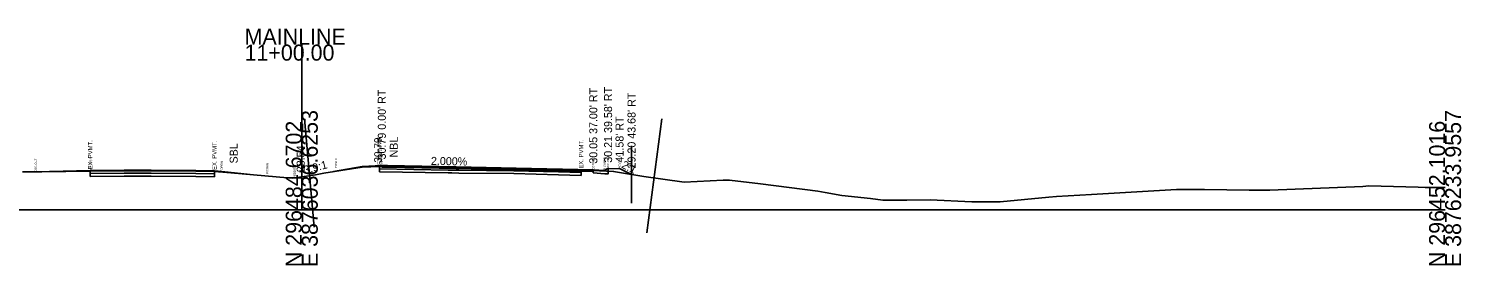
# Model space of a CAD drawing. Extents: x 14823 to 15251, y 114839 to 117377.
# Drawn here: x 15000.6 to 15251.2, y 116838.7 to 116880.1 of the extents above; entities that cross this region are included whole.
import ezdxf

# ---------------------------------------------------------------- set-up
doc = ezdxf.new("R2010")
doc.units = 0
for name, color, linetype in [('Default', 7, 'Continuous'), ('Level 1', 7, 'Continuous'), ('Level 10', 7, 'Continuous'), ('Level 11', 7, 'Continuous'), ('Level 2', 7, 'Continuous'), ('Level 25', 7, 'Continuous'), ('Level 3', 7, 'Continuous'), ('Level 4', 7, 'Continuous'), ('Level 42', 7, 'Continuous'), ('Level 49', 7, 'Continuous'), ('Level 50', 7, 'Continuous'), ('Level 51', 7, 'Continuous'), ('Level 52', 7, 'Continuous'), ('Level 53', 7, 'Continuous'), ('Level 56', 7, 'Continuous'), ('Level 59', 7, 'Continuous'), ('Level 63', 7, 'Continuous')]:
    doc.layers.add(name, color=color, linetype=linetype)

msp = doc.modelspace()

# ---------------------------------------------------------------- linework, layer by layer
at = {"layer": 'Default'}
for p, q in [((15048.86, 116864.32), (15050.53, 116845.37)), ((15111.37, 116864.32), (15108.71, 116844.37))]:
    msp.add_line(p, q, dxfattribs=at)
at = {"layer": 'Level 1'}
for p, q in [((15058.93, 116855.83), (15061.94, 116855.95)), ((15061.94, 116855.95), (15073.95, 116855.76)), ((14999.53, 116855.01), (15002.9, 116855.04)), ((15002.9, 116855.04), (15011.36, 116855.15)), ((15011.36, 116855.15), (15017.29, 116855.2)), ((15017.29, 116855.2), (15022.03, 116855.22)), ((15022.03, 116855.22), (15029.81, 116855.13)), ((15029.81, 116855.13), (15033.09, 116855.08)), ((15033.09, 116855.08), (15035.95, 116854.84)), ((15035.95, 116854.84), (15045.87, 116854.01)), ((15045.87, 116854.01), (15046.83, 116853.93)), ((15046.83, 116853.93), (15048.36, 116854.16)), ((15048.36, 116854.16), (15050.75, 116854.52)), ((15050.75, 116854.52), (15052.24, 116854.82)), ((15052.24, 116854.82), (15058.93, 116855.83)), ((15073.95, 116855.76), (15074.62, 116855.75)), ((15074.62, 116855.75), (15075.83, 116855.73)), ((15075.83, 116855.73), (15085.45, 116855.64)), ((15085.45, 116855.64), (15093.25, 116855.44)), ((15093.25, 116855.44), (15097.22, 116855.31)), ((15097.22, 116855.31), (15100.42, 116855.2)), ((15100.42, 116855.2), (15102.92, 116855.1)), ((15102.92, 116855.1), (15108.21, 116854.2)), ((15108.21, 116854.2), (15115.27, 116853.25)), ((15115.27, 116853.25), (15122.1, 116853.57)), ((15122.1, 116853.57), (15123.17, 116853.55)), ((15123.17, 116853.55), (15128.63, 116852.92)), ((15128.63, 116852.92), (15138.66, 116851.65)), ((15138.66, 116851.65), (15139.93, 116851.41)), ((15139.93, 116851.41), (15142.83, 116850.9)), ((15142.83, 116850.9), (15147.86, 116850.35)), ((15180.41, 116850.71), (15186.53, 116851.07)), ((15186.53, 116851.07), (15201.36, 116851.94)), ((15201.36, 116851.94), (15206.26, 116851.94)), ((15206.26, 116851.94), (15214.11, 116851.85)), ((15214.11, 116851.85), (15217.71, 116851.84)), ((15217.71, 116851.84), (15233.99, 116852.48)), ((15233.99, 116852.48), (15235.04, 116852.56)), ((15235.04, 116852.56), (15243.68, 116852.36)), ((15243.68, 116852.36), (15244.87, 116852.32)), ((15244.87, 116852.32), (15247.05, 116852.31)), ((15247.05, 116852.31), (15248.36, 116852.3)), ((15147.86, 116850.35), (15150.03, 116850.06)), ((15150.03, 116850.06), (15154.18, 116850.07)), ((15154.18, 116850.07), (15158.27, 116850.14)), ((15158.27, 116850.14), (15165.56, 116849.81)), ((15165.56, 116849.81), (15165.94, 116849.79)), ((15165.94, 116849.79), (15170.55, 116849.78)), ((15170.55, 116849.78), (15179.05, 116850.6)), ((15179.05, 116850.6), (15180.41, 116850.71))]:
    msp.add_line(p, q, dxfattribs=at)
at = {"layer": 'Level 10'}
for p, q in [((15062.37, 116856.03), (15062.37, 116856.15)), ((15062.37, 116855.86), (15062.37, 116856.03)), ((15062.37, 116856.03), (15063.36, 116856.01)), ((15062.37, 116855.86), (15063.36, 116855.84)), ((15075.37, 116855.77), (15063.36, 116856.01)), ((15034.36, 116855.1), (15034.36, 116854.97)), ((15075.37, 116855.6), (15063.36, 116855.84)), ((15085.86, 116855.56), (15075.37, 116855.77)), ((15085.86, 116855.39), (15075.37, 116855.6)), ((15085.86, 116855.56), (15099.36, 116855.29)), ((15085.86, 116855.39), (15099.36, 116855.12)), ((15099.36, 116855.29), (15099.36, 116855.41)), ((15099.36, 116855.12), (15099.36, 116855.29))]:
    msp.add_line(p, q, dxfattribs=at)
at = {"layer": 'Level 11'}
for p, q in [((15058.93, 116855.95), (15058.93, 116855.83)), ((15099.36, 116854.83), (15099.36, 116855.41)), ((15101.36, 116854.66), (15099.36, 116854.83)), ((15101.95, 116854.66), (15101.36, 116854.66)), ((15101.95, 116855.58), (15101.95, 116854.66))]:
    msp.add_line(p, q, dxfattribs=at)
at = {"layer": 'Level 2'}
for p, q in [((15062.37, 116856.15), (15058.93, 116855.95)), ((15062.37, 116856.15), (15063.36, 116856.13)), ((15063.36, 116856.13), (15075.37, 116855.89)), ((15075.37, 116855.89), (15085.86, 116855.68)), ((15011.36, 116855.27), (15001.83, 116855.03)), ((15011.36, 116855.27), (15017.29, 116855.33)), ((15017.29, 116855.33), (15022.03, 116855.34)), ((15022.03, 116855.34), (15029.81, 116855.26)), ((15029.81, 116855.26), (15033.09, 116855.21)), ((15033.1, 116855.21), (15034.36, 116855.1)), ((15085.86, 116855.68), (15099.36, 116855.41))]:
    msp.add_line(p, q, dxfattribs=at)
at = {"layer": 'Level 25'}
msp.add_line((15106.05, 116859.57), (15106.05, 116849.57), dxfattribs=at)
at = {"layer": 'Level 3'}
for p, q in [((15058.93, 116855.95), (15053.93, 116855.07)), ((15034.36, 116855.1), (15039.36, 116854.55)), ((15099.36, 116855.41), (15101.36, 116855.24)), ((15101.36, 116855.33), (15101.78, 116855.58)), ((15101.36, 116855.24), (15101.36, 116855.33)), ((15101.78, 116855.58), (15101.95, 116855.58))]:
    msp.add_line(p, q, dxfattribs=at)
at = {"layer": 'Level 4'}
for p, q in [((15101.95, 116855.58), (15103.95, 116855.62)), ((15103.95, 116855.62), (15106.05, 116854.57))]:
    msp.add_line(p, q, dxfattribs=at)
at = {"layer": 'Level 50'}
for points in [[(15053.93, 116855.07), (15058.93, 116855.83), (15061.94, 116855.95), (15073.95, 116855.76), (15074.62, 116855.75), (15075.83, 116855.73), (15085.45, 116855.64), (15093.25, 116855.44), (15097.22, 116855.31), (15099.36, 116855.24), (15099.36, 116855.41), (15085.86, 116855.68), (15075.37, 116855.89), (15063.36, 116856.13), (15062.37, 116856.15), (15058.93, 116855.95)], [(15099.36, 116854.83), (15099.36, 116855.24), (15100.42, 116855.2), (15101.95, 116855.14), (15101.95, 116854.66), (15101.36, 116854.66)], [(15101.95, 116855.14), (15102.92, 116855.1), (15106.05, 116854.57), (15103.95, 116855.62), (15101.95, 116855.58)]]:
    msp.add_lwpolyline(points, close=True, dxfattribs=at)
at = {"layer": 'Level 59'}
for p, q in [((15061.94, 116855.95), (15061.94, 116855.53)), ((15011.36, 116855.15), (15011.36, 116854.73)), ((15011.36, 116854.73), (15017.29, 116854.78)), ((15011.36, 116854.73), (15011.36, 116854.23)), ((15011.36, 116854.23), (15017.29, 116854.28)), ((15017.29, 116854.78), (15022.03, 116854.8)), ((15017.29, 116854.28), (15022.03, 116854.3)), ((15022.03, 116854.8), (15029.81, 116854.72)), ((15022.03, 116854.3), (15029.81, 116854.22)), ((15029.81, 116854.72), (15033.09, 116854.67)), ((15029.81, 116854.22), (15033.09, 116854.17)), ((15033.09, 116854.67), (15033.09, 116855.08)), ((15033.09, 116854.67), (15033.09, 116854.67)), ((15033.09, 116854.17), (15033.09, 116854.67)), ((15033.09, 116854.17), (15033.09, 116854.17)), ((15061.94, 116855.53), (15073.95, 116855.35)), ((15061.94, 116855.53), (15061.94, 116855.03)), ((15061.94, 116855.03), (15073.95, 116854.85)), ((15073.95, 116855.35), (15074.62, 116855.33)), ((15073.95, 116854.85), (15074.62, 116854.83)), ((15074.62, 116855.33), (15075.83, 116855.31)), ((15074.62, 116854.83), (15075.83, 116854.81)), ((15075.83, 116855.31), (15085.45, 116855.23)), ((15075.83, 116854.81), (15085.45, 116854.73)), ((15085.45, 116855.23), (15093.25, 116855.03)), ((15085.45, 116854.73), (15093.25, 116854.53)), ((15093.25, 116855.03), (15097.22, 116854.89)), ((15093.25, 116854.53), (15097.22, 116854.39)), ((15097.22, 116854.89), (15097.22, 116855.31)), ((15097.22, 116854.39), (15097.22, 116854.89))]:
    msp.add_line(p, q, dxfattribs=at)
at = {"layer": 'Level 63'}
for p, q in [((15048.36, 116848.36), (15048.36, 116877.29)), ((14848.36, 116848.36), (15048.36, 116848.36)), ((15048.36, 116848.36), (15248.36, 116848.36))]:
    msp.add_line(p, q, dxfattribs=at)

# ---------------------------------------------------------------- texts
at = {"layer": 'Level 42'}
for s, p in [('NBL', (15065.16, 116857.55)), ('SBL', (15037.16, 116856.5))]:
    msp.add_text(s, height=1.4, rotation=90, dxfattribs=at).set_placement(p)
at = {"layer": 'Level 49'}
msp.add_text('2.000%', height=1.4, rotation=358.8542, dxfattribs=at).set_placement((15070.95, 116856.26))
at = {"layer": 'Level 50'}
for s, rotation, p in [('3.9:1', 14.2666, (15048.91, 116854.65)), ('2:1', 333.435, (15104.18, 116855.82))]:
    msp.add_text(s, height=1.4, rotation=rotation, dxfattribs=at).set_placement(p)
at = {"layer": 'Level 51'}
msp.add_text('28.54', height=1.4, rotation=90, dxfattribs=at).set_placement((15048.87, 116854.96))
at = {"layer": 'Level 52'}
for s, p in [("30.79 0.00' RT", (15063.07, 116857.2)), ("30.05 37.00' RT", (15100.06, 116856.46)), ("30.21 39.58' RT", (15102.65, 116856.63)), ("29.20 43.68' RT", (15106.75, 116855.62)), ("41.58' RT", (15104.65, 116856.67))]:
    msp.add_text(s, height=1.4, rotation=90, dxfattribs=at).set_placement(p)
at = {"layer": 'Level 53'}
for p in [(15062.31, 116855.95), (15011.73, 116855.15), (15033.46, 116855.08), (15097.59, 116855.31)]:
    msp.add_text(' EX. PVMT.', height=0.75, rotation=90, dxfattribs=at).set_placement(p)
at = {"layer": 'Level 56'}
for s, p in [('EOSLOUT', (15002, 116855.03)), ('EOPLOUT', (15011.53, 116855.27)), ('EOPRIN', (15034.54, 116855.1)), ('EOSRIN', (15042.54, 116854.7)), ('EOSLIN', (15054.54, 116855.75)), ('EOPLIN', (15062.54, 116856.15)), ('EOPROUT', (15099.54, 116855.41)), ('FLCURBR', (15101.54, 116855.33)), ('BKCURBR', (15102.12, 116855.58)), ('RCVRBLR', (15104.12, 116855.62)), ('FRDTCHR', (15106.22, 116854.57)), ('MEDDIT', (15047.29, 116853.91))]:
    msp.add_text(s, height=0.35, rotation=90, dxfattribs=at).set_placement(p)
at = {"layer": 'Level 63'}
for s, p in [('MAINLINE', (15038.37, 116877.29)), ('11+00.00', (15038.36, 116874.49))]:
    msp.add_text(s, height=2.8, dxfattribs=at).set_placement(p)
for s, height, p in [('N 296484.6702', 2.8, (15048.36, 116838.36)), ('E 3876036.6253', 2.8, (15051.16, 116838.36)), ('N 296452.1016', 2.8, (15248.36, 116838.36)), ('E 3876233.9557', 2.8, (15251.16, 116838.36)), (' 30.79', 1.32, (15062.36, 116856.15))]:
    msp.add_text(s, height=height, rotation=90, dxfattribs=at).set_placement(p)

doc.saveas('drawing.dxf')
